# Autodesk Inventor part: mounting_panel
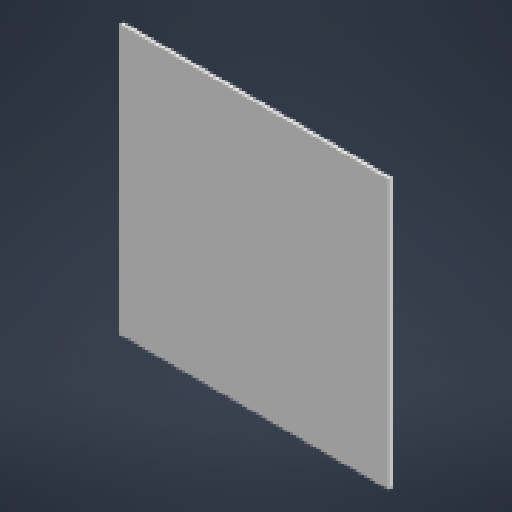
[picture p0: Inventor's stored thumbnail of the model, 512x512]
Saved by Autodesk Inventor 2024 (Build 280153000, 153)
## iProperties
Created: 2023-09
Part Number: mounting_panel
Material: Generic
Document SubType Name: Modeling
Designer: mammothbane
Density: 1 g/cm^3
Appearance: Default
Author: mammothbane
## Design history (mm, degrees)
sketch "Sketch1"
  geometry: L1 (-200, -200)-(200, -200); L2 (200, -200)-(200, 200); L3 (200, 200)-(-200, 200); L4 (-200, 200)-(-200, -200); L5 (-200, -200)-(200, 200); L6 (200, -200)-(-200, 200); 1 further point
  constraints: 12 end point, 2 midpoint, 2 parallel, 1 horizontal, 1 perpendicular
  dimensions: "height" = 400 distance of L3.end L2.end; "width" = 400 distance of L2.end L1.end
extrude "Extrusion1" new body sketch "Sketch1" taper "d3" = 0 deg; distance "thickness" = 5
body "Solid1"
